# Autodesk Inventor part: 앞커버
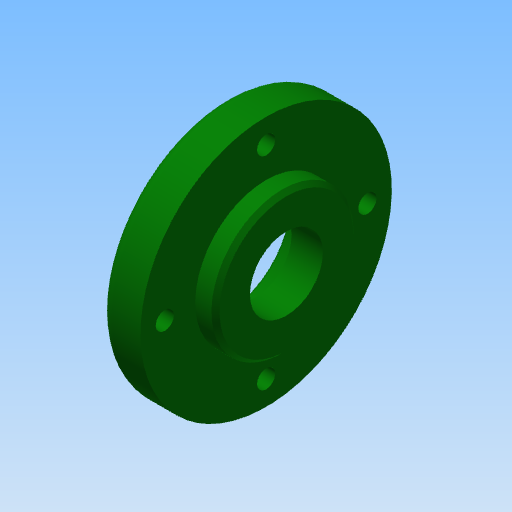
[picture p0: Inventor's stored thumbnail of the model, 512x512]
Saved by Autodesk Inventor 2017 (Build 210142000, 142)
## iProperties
Created: 2015-12
Part Number: 앞커버
Document SubType Name: Modeling
Designer: mdu
Density: 2.71 g/cm^3
Material: 알루미늄 6061
Appearance: 진녹색
Mass: 70.9292 g
Surface Area: 93.9296 cm^2
Volume: 26.1731 cm^3
Author: mdu
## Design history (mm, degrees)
sketch "스케치1"
  geometry: L1 (-7.5, 0)-(7.5, 0); L2 (-7.5, 0)-(-7.5, 31); L3 (-7.5, 31)-(2.5, 31); L4 (2.5, 31)-(2.5, 17.5); L5 (2.5, 17.5)-(7.5, 17.5); L6 (7.5, 17.5)-(7.5, 0); 2 further points
  constraints: 12 end point, 3 perpendicular, 1 coincident, 1 horizontal, 1 midpoint, 1 parallel
  dimensions: "d0" = 15 distance of L1.start L1.end; "d1" = 62 diameter of L3 L1; "d2" = 35 diameter of L5 L1; "d5" = 10 distance of L2.end L3.end
revolve "회전1" sketch "스케치1" stored, may be unused: angle "d6" = 90 deg
sketch "스케치2" dims "d42" = 50
  geometry: 3 further points
  constraints: 2 vertical alignment, 1 coincident, 2 other
hole "구멍1" sketch "스케치2" at (0, 25) diameter "d8" = 4.5; stored, may be unused: countersink angle "d12" = 90 deg, drill point angle "d14" = 118 deg; dims "d9" = 6, "d10" = 8, "d11" = 4.4, "d13" = 8
hole "구멍2" diameter "d20" = 18; stored, may be unused: countersink angle "d24" = 90 deg, drill point angle "d26" = 0 deg; dims "d18" = 10, "d19" = 10, "d21" = 6, "d22" = 8, "d23" = 4.4, "d25" = 8
hole "구멍3" diameter "d34" = 30; stored, may be unused: countersink angle "d38" = 90 deg, drill point angle "d40" = 0 deg; dims "d32" = 10, "d33" = 10, "d35" = 6, "d36" = 4, "d37" = 2, "d39" = 7.3
fillet "모깎기1" dims "d27" = 3, "d41" = 0.3
chamfer "모따기1" distance "d29" = 1; stored, may be unused: second distance "d30" = 2, angle "d31" = 45 deg
node "솔리드1"
pattern_circular "원형 패턴1" dims angle "d16" = 360 deg
